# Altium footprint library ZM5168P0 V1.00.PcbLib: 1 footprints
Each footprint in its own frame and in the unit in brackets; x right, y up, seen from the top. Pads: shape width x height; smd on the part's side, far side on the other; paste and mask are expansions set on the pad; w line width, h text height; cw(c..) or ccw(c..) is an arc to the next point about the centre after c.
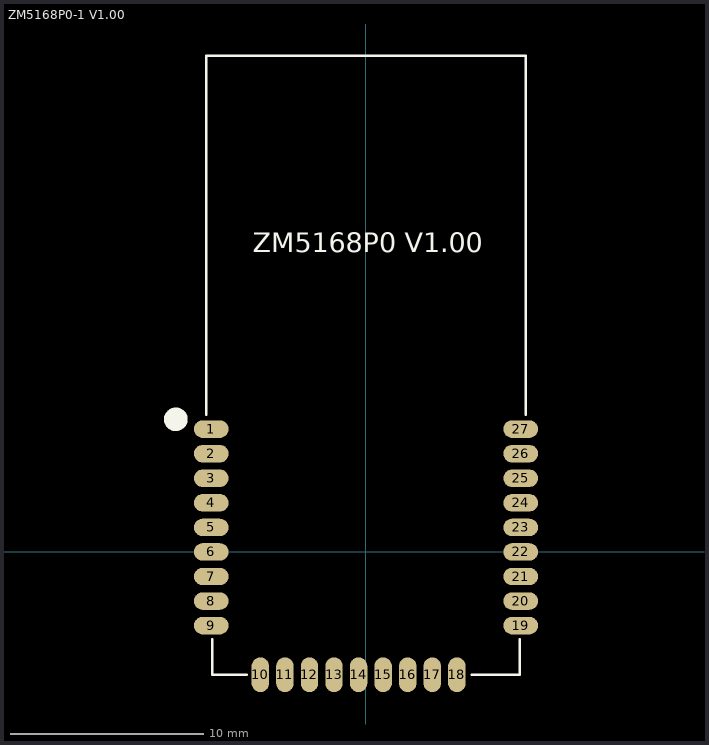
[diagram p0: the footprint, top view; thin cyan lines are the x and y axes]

## ZM5168P0-1 V1.00 [mm]
pads (27):
  oval 1.8x0.9 smd: 1(-8,6.35) 2(-8,5.08) 3(-8,3.81) 4(-8,2.54) 5(-8,1.27) 6(-8,0) 7(-8,-1.27) 8(-8,-2.54) 9(-8,-3.81) 19(8,-3.81) 20(8,-2.54) 21(8,-1.27) 22(8,0) 23(8,1.27) 24(8,2.54) 25(8,3.81) 26(8,5.08) 27(8,6.35)
  oval 0.9x1.8 smd: 10(-5.46,-6.35) 11(-4.19,-6.35) 12(-2.92,-6.35) 13(-1.65,-6.35) 14(-0.38,-6.35) 15(0.89,-6.35) 16(2.16,-6.35) 17(3.43,-6.35) 18(4.7,-6.35)
Top Overlay:
  circle w0.61: c-9.83,6.858 r0.305
  lines w0.127: -8.254,7.087 -8.254,25.65 8.254,25.65 8.254,7.087 ; -7.949,-4.521 -7.949,-6.35 -6.171,-6.35 ; 5.462,-6.35 7.949,-6.35 7.949,-4.521
  text "ZM5168P0 V1.00" at -5.842,15.494 h1.02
